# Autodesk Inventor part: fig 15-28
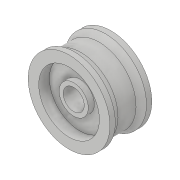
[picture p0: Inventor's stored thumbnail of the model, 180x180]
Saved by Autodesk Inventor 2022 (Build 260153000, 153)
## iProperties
Created: 2018-03
Part Number: fig 15-28
Material: Generic
Document SubType Name: Modeling
Designer: CADCIM 00
Density: 1 g/cm^3
Appearance: Default
Author: CADCIM 00
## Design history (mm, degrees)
sketch "Sketch1"
  geometry: L1 (3.327, 5.31)-(3.327, -4.99); L2 (3.327, -4.99)-(4.606, -4.99); L3 (4.606, -4.99)-(4.606, -3.071); L4 (4.606, -3.071)-(9.597, -3.071); L5 (9.597, -3.071)-(9.597, -6.462); L6 (9.597, -6.462)-(12.924, -6.462); L7 (12.924, -6.462)-(12.924, -4.766); L8 (12.924, -4.766)-(11.708, -2.687); L9 (11.708, -2.687)-(11.708, 0.16); L10 (11.708, 0.16)-(3.327, 0.16); L11 (3.327, 5.31)-(4.606, 5.31); L12 (4.606, 5.31)-(4.606, 3.391); L13 (4.606, 3.391)-(9.597, 3.391); L14 (9.597, 3.391)-(9.597, 6.782); L15 (9.597, 6.782)-(12.924, 6.782); L16 (12.924, 6.782)-(12.924, 5.086); L17 (12.924, 5.086)-(11.708, 3.007); L18 (11.708, 3.007)-(11.708, 0.16); L19 (0, 7.901)-(0, -9.532); 1 further point
  constraints: 38 end point, 7 symmetric about line, 6 perpendicular, 2 vertical, 1 midpoint, 1 parallel
revolve "Revolution1" sketch "Sketch1" stored, may be unused: angle "d0" = 90 deg
body "Solid1"
